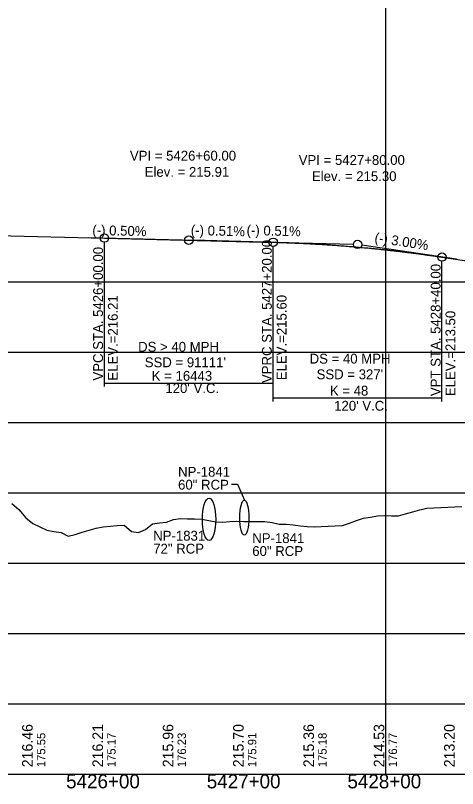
# Model space of a CAD drawing. Extents: x 69 to 2003113, y 512 to 837401.
# Drawn here: x 1886474 to 1886788, y 775979 to 776528 of the extents above; entities that cross this region are included whole.
import ezdxf

# ---------------------------------------------------------------- set-up
doc = ezdxf.new("R2010")
doc.units = 0
for name, color, linetype in [('BR_AUTO DIMENSION', 7, 'Continuous'), ('BR_BORDER LINES', 7, 'Continuous'), ('BR_CENTER LINE BASELINE', 7, 'Continuous'), ('BR_CONCRETE', 7, 'Continuous'), ('BR_GRID DOTS', 7, 'Continuous'), ('BR_GRID LINES', 7, 'Continuous'), ('BR_TEXT', 7, 'Continuous'), ('RD_HC_Points', 7, 'Continuous'), ('RD_SHT_ID', 7, 'Continuous'), ('RD_SHT_IplotShp', 7, 'Continuous'), ('RD_XS_PaveShd', 7, 'Continuous')]:
    doc.layers.add(name, color=color, linetype=linetype)

msp = doc.modelspace()

# ---------------------------------------------------------------- linework, layer by layer
at = {"layer": 'BR_AUTO DIMENSION'}
for p, q in [((1886736.94, 775989.14), (1886736.94, 777706.15)), ((1883686.1, 776339.14), (1888825.1, 776339.14)), ((1883686.1, 776289.14), (1888825.1, 776289.14)), ((1883686.1, 776239.14), (1888825.1, 776239.14)), ((1883686.1, 776189.14), (1888825.1, 776189.14)), ((1883686.1, 776139.14), (1888825.1, 776139.14)), ((1883686.1, 776089.14), (1888825.1, 776089.14)), ((1883686.1, 776039.14), (1888825.1, 776039.14)), ((1883636.94, 775989.14), (1888825.1, 775989.14))]:
    msp.add_line(p, q, dxfattribs=at)
at = {"layer": 'BR_BORDER LINES'}
msp.add_line((1883686.1, 775989.14), (1889486.1, 775989.14), dxfattribs=at)
at = {"layer": 'BR_CENTER LINE BASELINE'}
for p, q in [((1886525.96, 776370.46), (1886593.94, 776368.76)), ((1886667.91, 776366.88), (1886599.94, 776368.61)), ((1886645.96, 776367.44), (1886713.94, 776365.71)), ((1886787.15, 776355.1), (1886719.9, 776365.19))]:
    msp.add_line(p, q, dxfattribs=at)
for centre in [(1886596.94, 776368.69), (1886716.94, 776365.63)]:
    msp.add_circle(centre, 3, dxfattribs=at)
at = {"layer": 'BR_GRID DOTS'}
for p, q in [((1886536.94, 776264.66), (1886536.94, 776367.19)), ((1886656.94, 776264.66), (1886656.94, 776364.16)), ((1886656.94, 776254.13), (1886656.94, 776364.16)), ((1886776.94, 776254.13), (1886776.94, 776353.63)), ((1886536.94, 776267.16), (1886656.94, 776267.16)), ((1886656.94, 776256.63), (1886776.94, 776256.63))]:
    msp.add_line(p, q, dxfattribs=at)
for centre in [(1886536.94, 776370.19), (1886656.94, 776367.16), (1886776.94, 776356.63)]:
    msp.add_circle(centre, 3, dxfattribs=at)
at = {"layer": 'BR_GRID LINES'}
for p, q in [((1886440.45, 776372.61), (1886536.94, 776370.19)), ((1886656.94, 776367.16), (1886656.94, 776367.16)), ((1886776.94, 776356.63), (1887166.94, 776298.14))]:
    msp.add_line(p, q, dxfattribs=at)
for points in [[(1886536.94, 776370.19), (1886539.34, 776370.13), (1886541.74, 776370.07), (1886544.14, 776370.01), (1886546.54, 776369.95), (1886548.94, 776369.89), (1886551.34, 776369.83), (1886553.74, 776369.77), (1886556.14, 776369.71), (1886558.54, 776369.65), (1886560.94, 776369.59), (1886563.34, 776369.53), (1886565.74, 776369.47), (1886568.14, 776369.41), (1886570.54, 776369.35), (1886572.94, 776369.29), (1886575.34, 776369.22), (1886577.74, 776369.16), (1886580.14, 776369.1), (1886582.54, 776369.04), (1886584.94, 776368.98), (1886587.34, 776368.92), (1886589.74, 776368.86), (1886592.14, 776368.8), (1886594.54, 776368.74), (1886596.94, 776368.68), (1886599.34, 776368.62), (1886601.74, 776368.56), (1886604.14, 776368.5), (1886606.54, 776368.44), (1886608.94, 776368.38), (1886611.34, 776368.32), (1886613.74, 776368.26), (1886616.14, 776368.19), (1886618.54, 776368.13), (1886620.94, 776368.07), (1886623.34, 776368.01), (1886625.74, 776367.95), (1886628.14, 776367.89), (1886630.54, 776367.83), (1886632.94, 776367.77), (1886635.34, 776367.71), (1886637.74, 776367.65), (1886640.14, 776367.59), (1886642.54, 776367.53), (1886644.94, 776367.46), (1886647.34, 776367.4), (1886649.74, 776367.34), (1886652.14, 776367.28), (1886654.54, 776367.22), (1886656.94, 776367.16)], [(1886656.94, 776367.16), (1886659.34, 776367.1), (1886661.74, 776367.03), (1886664.14, 776366.95), (1886666.54, 776366.87), (1886668.94, 776366.78), (1886671.34, 776366.69), (1886673.74, 776366.59), (1886676.14, 776366.48), (1886678.54, 776366.37), (1886680.94, 776366.25), (1886683.34, 776366.13), (1886685.74, 776366), (1886688.14, 776365.86), (1886690.54, 776365.72), (1886692.94, 776365.57), (1886695.34, 776365.42), (1886697.74, 776365.26), (1886700.14, 776365.09), (1886702.54, 776364.92), (1886704.94, 776364.74), (1886707.34, 776364.56), (1886709.74, 776364.37), (1886712.14, 776364.17), (1886714.54, 776363.97), (1886716.94, 776363.77), (1886719.34, 776363.55), (1886721.74, 776363.33), (1886724.14, 776363.11), (1886726.54, 776362.88), (1886728.94, 776362.64), (1886731.34, 776362.39), (1886733.74, 776362.15), (1886736.14, 776361.89), (1886738.54, 776361.63), (1886740.94, 776361.36), (1886743.34, 776361.09), (1886745.74, 776360.81), (1886748.14, 776360.52), (1886750.54, 776360.23), (1886752.94, 776359.94), (1886755.34, 776359.63), (1886757.74, 776359.32), (1886760.14, 776359.01), (1886762.54, 776358.69), (1886764.94, 776358.36), (1886767.34, 776358.03), (1886769.74, 776357.69), (1886772.14, 776357.34), (1886774.54, 776356.99), (1886776.94, 776356.63)]]:
    msp.add_spline(points, degree=3, dxfattribs=at)
at = {"layer": 'BR_TEXT'}
for points in [[(1886471.1, 776181.65), (1886476.1, 776177.21), (1886481.1, 776171.34), (1886486.1, 776167.3), (1886491.1, 776164.92), (1886496.1, 776162.49), (1886501.1, 776161.54), (1886506.1, 776160.95), (1886511.1, 776158.36), (1886516.1, 776159.63), (1886521.1, 776161.18), (1886526.1, 776162.59), (1886531.1, 776164.1), (1886536.1, 776164.9), (1886541.1, 776165.33), (1886546.1, 776165.9), (1886551.1, 776166.25), (1886556.1, 776161.63), (1886561.1, 776161.02), (1886566.1, 776163.14), (1886571.1, 776166.98), (1886576.1, 776167.8), (1886581.1, 776168.32), (1886586.1, 776170.19), (1886591.1, 776170.81), (1886596.1, 776170.72), (1886601.1, 776170.56), (1886606.1, 776170.41), (1886611.1, 776169.47), (1886616.1, 776168.46), (1886621.1, 776168.26), (1886626.1, 776168.76), (1886631.1, 776168.95), (1886636.1, 776168.69), (1886641.1, 776168.71), (1886646.1, 776168.83), (1886651.1, 776168.86), (1886656.1, 776167.98), (1886661.1, 776166.89), (1886666.1, 776166.93), (1886671.1, 776166.39), (1886676.1, 776165.78), (1886681.1, 776165.16), (1886686.1, 776165.02)], [(1886686.1, 776165.02), (1886691.1, 776165.2), (1886696.1, 776165.49), (1886701.1, 776165.79), (1886706.1, 776165.83), (1886711.1, 776167.61), (1886716.1, 776169.38), (1886721.1, 776171.16), (1886726.1, 776171.84), (1886731.1, 776172.74), (1886736.1, 776173.01), (1886741.1, 776172.89), (1886746.1, 776172.87), (1886751.1, 776174.27), (1886756.1, 776175.66), (1886761.1, 776177.06), (1886766.1, 776178.3), (1886771.1, 776178.55), (1886776.1, 776178.75), (1886781.1, 776178.96), (1886786.1, 776179.17), (1886791.1, 776179.38)]]:
    msp.add_lwpolyline(points, dxfattribs=at)
at = {"layer": 'RD_XS_PaveShd'}
msp.add_lwpolyline([(1886627.3, 776195.31), (1886631.62, 776195.31), (1886636.47, 776183.88)], dxfattribs=at)
for centre, major_axis, ratio in [((1886611.34, 776170.29), (0, 15), 0.316718), ((1886636.47, 776171.41), (0, 12.47), 0.261899)]:
    msp.add_ellipse(centre, major_axis=major_axis, ratio=ratio, dxfattribs=at)

# ---------------------------------------------------------------- texts
at = {"layer": 'BR_CENTER LINE BASELINE'}
for s, rotation, p in [('(-) 0.50%', 358.564, (1886528.3, 776372.41)), ('(-) 0.51%', 358.5431, (1886598.31, 776372.37)), ('(-) 0.51%', 358.5431, (1886637.96, 776372.37)), ('(-) 3.00%', 351.4697, (1886728.67, 776367.19))]:
    msp.add_text(s, height=7, rotation=rotation, dxfattribs=at).set_placement(p)
at = {"layer": 'BR_CONCRETE'}
for s, height, p in [('VPRC STA. 5427+20.00 ', 7, (1886655.94, 776267.13)), ('VPC STA. 5426+00.00 ', 7, (1886535.94, 776268.89)), ('VPT STA. 5428+40.00 ', 7, (1886775.94, 776257.87)), ('ELEV.=216.21', 7, (1886546.44, 776268.89)), ('ELEV.=215.60', 7, (1886666.44, 776269.16)), ('ELEV.=213.50', 7, (1886786.44, 776257.87)), ('175.55', 6, (1886494.94, 775994.14)), ('175.17', 6, (1886544.94, 775994.14)), ('176.23', 6, (1886594.94, 775994.14)), ('175.91', 6, (1886644.94, 775994.14)), ('175.18', 6, (1886694.94, 775994.14)), ('176.77', 6, (1886744.94, 775994.14))]:
    msp.add_text(s, height=height, rotation=90, dxfattribs=at).set_placement(p)
at = {"layer": 'BR_GRID DOTS'}
for s, p in [('DS > 40 MPH', (1886560.9, 776289.4)), ('DS = 40 MPH', (1886682.87, 776280.98)), ("SSD = 91111'", (1886565.63, 776278.38)), ('K = 16443', (1886570.6, 776268.76)), ("SSD = 327'", (1886687.81, 776269.84)), ("120' V.C.", (1886580.29, 776260.02)), ('K = 48', (1886697.23, 776258.21)), ("120' V.C.", (1886700.29, 776247.49))]:
    msp.add_text(s, height=7, dxfattribs=at).set_placement(p)
at = {"layer": 'RD_HC_Points'}
for s, p in [('216.46', (1886485.94, 775994.14)), ('216.21', (1886535.94, 775994.14)), ('215.96', (1886585.94, 775994.14)), ('215.70', (1886635.94, 775994.14)), ('215.36', (1886685.94, 775994.14)), ('214.53', (1886735.94, 775994.14)), ('213.20', (1886785.94, 775994.14))]:
    msp.add_text(s, height=7.5, rotation=90, dxfattribs=at).set_placement(p)
at = {"layer": 'RD_SHT_ID'}
for s, p in [('5426+00', (1886509.72, 775979.14)), ('5427+00', (1886609.72, 775979.14)), ('5428+00', (1886709.72, 775979.14))]:
    msp.add_text(s, height=10, dxfattribs=at).set_placement(p)
at = {"layer": 'RD_SHT_IplotShp'}
for s, p in [('VPI = 5426+60.00', (1886555.08, 776425.19)), ('VPI = 5427+80.00', (1886675.08, 776422.13)), ('Elev. = 215.91', (1886565.58, 776413.69)), ('Elev. = 215.30', (1886684.49, 776410.63))]:
    msp.add_text(s, height=7, dxfattribs=at).set_placement(p)
at = {"layer": 'RD_XS_PaveShd'}
for s, p in [('NP-1841', (1886589.32, 776200.59)), ('60" RCP', (1886589.32, 776191.41)), ('NP-1831', (1886571.65, 776155.14)), ('NP-1841', (1886642.07, 776153.43)), ('72" RCP', (1886571.65, 776145.96)), ('60" RCP', (1886642.07, 776144.26))]:
    msp.add_text(s, height=7, dxfattribs=at).set_placement(p)

doc.saveas('drawing.dxf')
